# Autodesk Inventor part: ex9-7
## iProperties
Created: 2006-03
Part Number: ex9-7
Document SubType Name: Sheet Metal
Designer: Elise Moss
Author: Elise Moss
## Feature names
1. Plate1
2. Bend1
3. Plate2
4. Bend2
5. Cut1
